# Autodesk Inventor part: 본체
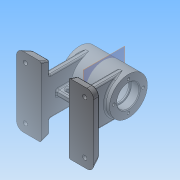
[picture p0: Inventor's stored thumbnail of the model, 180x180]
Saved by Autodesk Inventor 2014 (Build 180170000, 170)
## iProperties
Created: 2016-07
Part Number: 본체
Material: 일반
Document SubType Name: Modeling
Designer: net
Density: 1 g/cm^3
Appearance: 기본값
Mass: 183.105 g
Surface Area: 548.13 cm^2
Volume: 183.105 cm^3
Author: net
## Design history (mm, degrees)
sketch "스케치1"
  geometry: C1 r 27 at (0, 0); 1 further point
  constraints: 1 centre point, 1 coincident
  dimensions: "d0" = 54 diameter of C1
extrude "돌출1" new body sketch "스케치1" stored distance "d1" = 70; taper "d2" = 0 deg
node "작업 평면1"
node "작업 평면2"
sketch "스케치2"
  geometry: L1 (0, 53.184)-(0, -53.184); L2 (-55, 50)-(-20, 50); L3 (-20, 50)-(-20, -50); L4 (-20, -50)-(-55, -50); L5 (-55, -50)-(-55, 50); L6 (55, 50)-(20, 50); L7 (20, 50)-(20, -50); L8 (55, -50)-(55, 50); L9 (20, -50)-(55, -50); 2 further points
  constraints: 18 end point, 4 symmetric about line, 2 parallel, 1 coincident, 1 horizontal, 1 midpoint, 1 perpendicular, 1 vertical
  dimensions: "d5" = 55 distance between parallel lines of L1 L5; "d6" = 100 distance between parallel lines of L4 L2; "d7" = 50 distance from line of L4 point (0, 0); "d8" = 35 distance between parallel lines of L5 L3; "d9" = 106.36812 distance of L1.start L1.end
extrude "돌출2" join sketch "스케치2" distance "d10" = 12; taper "d11" = 0 deg
sketch "스케치3"
  geometry: L1 (20, 50)-(20, -50) reference; L2 (20, 27)-(28, 27); L3 (28, 27)-(28, -27); L4 (28, -27)-(20, -27); L5 (20, -27)-(20, 27); 2 further points
  constraints: 8 end point, 2 midpoint, 2 parallel, 1 horizontal, 1 perpendicular
  dimensions: "d12" = 8 distance between parallel lines of L5 L3; "d13" = 54 distance between parallel lines of L4 L2
extrude "돌출3" join sketch "스케치3" stored distance "d14" = 12; taper "d15" = 0 deg
sketch "스케치4"
  geometry: C1 r 27 at (0, 0) reference; C2 r 16 at (0, 0)
  constraints: 1 centre point, 1 coincident
  dimensions: "d16" = 32 diameter of C2
extrude "돌출4" cut sketch "스케치4" distance "d17" = 12; taper "d18" = 0 deg
sketch "스케치5"
  geometry: C1 r 16 at (0, 0) reference; C2 r 14 at (0, 0)
  constraints: 1 centre point, 1 coincident
  dimensions: "d19" = 28 diameter of C2
extrude "돌출5" cut sketch "스케치5" distance "d20" = 2; taper "d21" = 0 deg
sketch "스케치6"
  geometry: C1 r 14 at (0, 0) reference; C2 r 22 at (0, 0)
  constraints: 1 centre point, 1 coincident
  dimensions: "d22" = 44 diameter of C2
extrude "돌출6" cut sketch "스케치6" distance "d23" = 42; taper "d24" = 0 deg
sketch "스케치7" dims "d25" = 42
  geometry: L1 (0, 0)-(0, 21); C1 r 27 at (0, 0) reference; 1 further point
  constraints: 2 coincident, 2 end point, 1 vertical, 1 vertical alignment, 2 other
hole "구멍1" sketch "스케치7" at (0, 21) diameter "d26" = 4; stored, may be unused: countersink angle "d30" = 90 deg, drill point angle "d32" = 118 deg; dims "d27" = 6, "d28" = 4, "d29" = 2, "d31" = 10
feature "스레드1" dims "d33" = 8, "d34" = 0
feature "스레드2" dims "d38" = 8, "d39" = 0
sketch "스케치8"
  geometry: L1 (-35, -27)-(35, -27) reference; L2 (-27.796, -27)-(27.796, -27); L3 (27.796, -27)-(27.796, -48); L4 (27.796, -48)-(-27.796, -48); L5 (-27.796, -48)-(-27.796, -27); 2 further points
  constraints: 8 end point, 2 midpoint, 2 parallel, 1 horizontal, 1 perpendicular
  dimensions: "d43" = 21 distance of L4.end L2.start; "d44" = 55.59245 distance between parallel lines of L5 L3
extrude "돌출7" join sketch "스케치8" stored distance "d45" = 8; taper "d46" = 0 deg
fillet "모깎기1" dims "d47" = 2
sketch "스케치9"
  geometry: L1 (-18, -29)-(18, -29) reference; L2 (18, -46)-(-18, -46) reference; L3 (18, -29)-(18, -46) reference; L4 (0, -29)-(0, -46); L5 (-18, -48)-(18, -48) reference; L6 (-11.5, -34.5)-(11.5, -34.5); L7 (-11.5, -41.5)-(11.5, -41.5); L8 (20, -70)-(55, -70) reference; A1 r 3.5 centre (-11.5, -38) between (-11.5, -34.5) and (-11.5, -41.5); A2 r 3.5 centre (11.5, -38) between (11.5, -41.5) and (11.5, -34.5); 1 further point
  constraints: 6 end point, 4 point on circle, 2 centre point, 2 midpoint, 2 tangent, 1 horizontal alignment, 1 parallel, 1 perpendicular
  dimensions: "d48" = 7 diameter of A1; "d49" = 7 diameter of A2; "d50" = 11.5 distance from line of A1.centre L4; "d139" = 32 distance from line of L8 A2.centre; "d140" = 23 distance of A1.centre A2.centre
extrude "돌출8" cut sketch "스케치9" stored distance "d54" = 8; taper "d55" = 0 deg
fillet "모깎기2" dims "d56" = 2
node "작업 평면3"
sketch "스케치10"
  geometry: 1 further point
sketch "스케치11"
  geometry: L1 (-35, 27)-(-35, -27) reference; C1 r 5 at (-13, 0); 1 further point
  constraints: 1 centre point
  dimensions: "d59" = 10 diameter of C1; "d62" = 13 distance of point (0, 0) C1.centre; "d63" = 22 distance from line of L1 C1.centre
extrude "돌출9" join sketch "스케치11" stored distance "d64" = 8; taper "d65" = 0 deg
hole "구멍2" diameter "d68" = 5.188; stored, may be unused: countersink angle "d72" = 90 deg, drill point angle "d74" = 118 deg; dims "d66" = 10, "d67" = 10, "d69" = 10, "d70" = 4, "d71" = 2, "d73" = 10
sketch "스케치12"
  geometry: L1 (0, 0)-(0, -27); L2 (0, 0)-(15.898, -25.441); L3 (0, 0)-(30, 0); 1 further point
  constraints: 6 end point, 1 equal length, 1 horizontal, 1 vertical, 1 vertical alignment, 1 other
  dimensions: "d75" = 30 distance of L1.start L2.end; "d76" = 58 deg angle of L2 L3
node "작업 평면4"
sketch "스케치13"
  geometry: C1 r 6 at (0, 0); 1 further point
  constraints: 1 centre point, 1 coincident
  dimensions: "d77" = 12 diameter of C1
extrude "돌출10" join sketch "스케치13" stored distance "d78" = 8; taper "d79" = 0 deg
hole "구멍3" diameter "d82" = 5.188; stored, may be unused: countersink angle "d86" = 90 deg, drill point angle "d88" = 118 deg; dims "d80" = 10, "d81" = 10, "d83" = 10, "d84" = 4, "d85" = 2, "d87" = 10
node "작업 평면5"
fillet "모깎기3" dims "d94" = 2
fillet "모깎기4" dims "d95" = 2
chamfer "모따기1" distance "d96" = 1; stored, may be unused: second distance "d97" = 2, angle "d98" = 45 deg
chamfer "모따기2" distance "d99" = 1; stored, may be unused: second distance "d100" = 2, angle "d101" = 45 deg
node "작업 평면7"
sketch "스케치15"
  geometry: L1 (-35, 27)-(-35, -27) reference; L2 (35, 27)-(-35, 27) reference; 2 further points
  constraints: 1 other
  dimensions: "d107" = 35 distance from line of L1 point (0, 0); "d108" = 27 distance from line of L2 point (0, 0)
feature "엠보싱2" sketch "스케치15" dims "d5" = 55, "d6" = 100, "d7" = 50, "d8" = 35, "d9" = 106.36812, "d109" = 0.5, "d110" = 0
feature "면 기울기1" dims angle "d111" = 20 deg
feature "면 기울기2" dims angle "d112" = 20 deg
node "작업 평면9"
sketch "스케치16"
  geometry: L1 (100, 12)-(0, 12) reference; L2 (100, 0)-(100, 12) reference; L3 (100, 0)-(107, 0); L4 (100, 0)-(95.632, 12); L5 (100, 0)-(124.389, 0); L6 (95.632, 12)-(100, 12); L7 (100, 12)-(100, 0); 1 further point
  constraints: 10 end point, 2 collinear, 2 horizontal, 1 point on line
  dimensions: "d116" = 110 deg angle of L5 L4
extrude "돌출11" cut sketch "스케치16" stored distance "d117" = 10; taper "d118" = 0 deg
sketch "스케치17"
  geometry: L1 (95.632, 12)-(0, 12) reference; L2 (0, 0)-(0, 12) reference; L3 (0, 0)-(4.368, 12); L4 (0, 0)-(34.429, 0); L5 (4.368, 12)-(0, 12); L6 (0, 0)-(0, 12); 1 further point
  constraints: 8 end point, 1 collinear, 1 horizontal, 1 perpendicular, 1 point on line
  dimensions: "d119" = 70 deg angle of L4 L3
extrude "돌출12" cut sketch "스케치17" stored distance "d120" = 10; taper "d121" = 0 deg
fillet "모깎기5" dims "d122" = 10
fillet "모깎기7" dims "d124" = 10
fillet "모깎기6" dims "d123" = 10
fillet "모깎기8" dims "d125" = 2
fillet "모깎기9" dims "d126" = 2
fillet "모깎기10" dims "d127" = 0.3
fillet "모깎기11" dims "d128" = 0.3
fillet "모깎기12" dims "d129" = 3
sketch "스케치18"
  geometry: L1 (-49.232, -36.714)-(-49.232, 36.714) reference; L2 (-43.802, 37.5)-(-27.102, 37.5); L3 (-42.5, 40.094)-(-42.5, 21.811); L4 (-55, 40.603)-(-55, -40.603) reference; L5 (-20, 50)-(-45.603, 50) reference; C1 r 5 at (-42.5, 37.5); C2 r 3 at (-42.5, 37.5); 1 further point
  constraints: 4 end point, 2 centre point, 2 perpendicular, 2 point on line, 1 coincident
  dimensions: "d130" = 12.5 distance between parallel lines of L4 L3; "d131" = 12.5 distance between parallel lines of L2 L5; "d132" = 10 diameter of C1; "d133" = 6 diameter of C2
extrude "돌출13" cut sketch "스케치18" distance "d134" = 4; taper "d135" = 0 deg
extrude "돌출14" cut sketch "스케치18" stored distance "d136" = 4; taper "d137" = 0 deg
fillet "모깎기13" dims "d138" = 2
node "솔리드1"
mirror "대칭1"
mirror "대칭2"
pattern_circular "원형 패턴1" dims angle "d36" = 360 deg
mirror "대칭3"
pattern_circular "원형 패턴2" dims "d41" = 360 deg
mirror "대칭4"
mirror "대칭5"
mirror "대칭6"
mirror "대칭7"
node "작업 평면8"
other parameters: "d89" = 27, "d103" = -27, "d113" = -35
